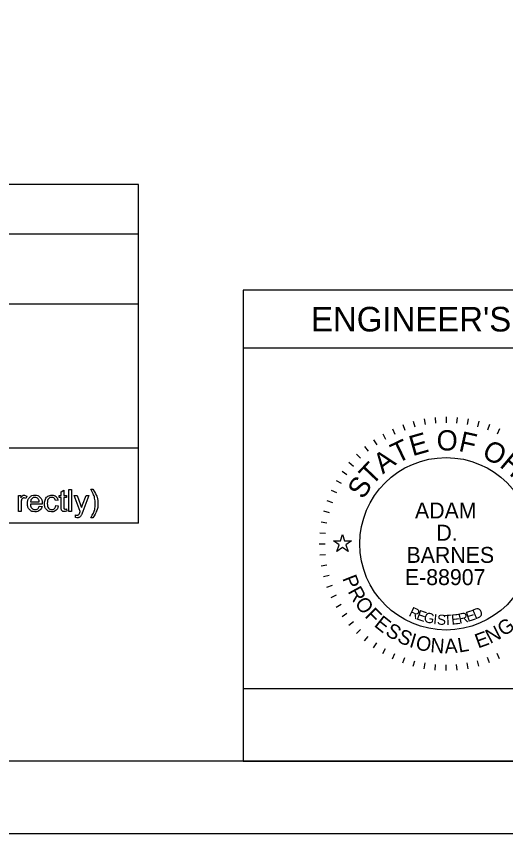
# Model space of a CAD drawing. Extents: x 0 to 34, y 0 to 22.
# Drawn here: x 5.78 to 9.16, y 0 to 5.64 of the extents above; entities that cross this region are included whole.
import ezdxf

# ---------------------------------------------------------------- set-up
doc = ezdxf.new("R2010")
doc.units = 0
for name, color, linetype in [('Default', 7, 'Continuous'), ('SH_Border', 7, 'Continuous'), ('SH_Cut_Line', 7, 'Continuous'), ('SH_Data', 7, 'Continuous'), ('SH_Text', 7, 'Continuous')]:
    doc.layers.add(name, color=color, linetype=linetype)

msp = doc.modelspace()

# ---------------------------------------------------------------- linework, layer by layer
at = {"layer": 'Default'}
msp.add_lwpolyline([(7.9736, 2.02), (8.0205, 2.02), (8.035, 2.0645), (8.0495, 2.02), (8.0964, 2.02), (8.0585, 1.9924), (8.073, 1.9478), (8.035, 1.9754), (7.997, 1.9478), (8.0115, 1.9924)], close=True, dxfattribs=at)
at = {"layer": 'SH_Border'}
msp.add_lwpolyline([(1.5, 21.5), (33.5, 21.5), (33.5, 0.5), (1.5, 0.5)], close=True, dxfattribs=at)
at = {"layer": 'SH_Cut_Line'}
msp.add_lwpolyline([(0, 0), (34, 0), (34, 22), (0, 22)], close=True, dxfattribs=at)
at = {"layer": 'SH_Data'}
for p, q in [((6.6275, 4.4803), (2.3775, 4.4803)), ((6.6275, 2.1428), (6.6275, 4.4803)), ((2.3775, 4.1387), (6.6275, 4.1387)), ((10.15, 3.75), (7.35, 3.75)), ((7.35, 3.75), (7.35, 0.5)), ((2.3775, 3.6553), (6.6275, 3.6553)), ((10.15, 3.35), (7.35, 3.35)), ((8.4507, 2.8222), (8.4644, 2.7846)), ((8.5235, 2.8452), (8.5339, 2.8065)), ((8.5981, 2.8617), (8.605, 2.8223)), ((8.6737, 2.8717), (8.6772, 2.8318)), ((8.75, 2.875), (8.75, 2.835)), ((8.8263, 2.8717), (8.8228, 2.8318)), ((8.9019, 2.8617), (8.895, 2.8223)), ((8.9765, 2.8452), (8.9661, 2.8065)), ((9.0493, 2.8222), (9.0356, 2.7846)), ((8.3802, 2.793), (8.3971, 2.7568)), ((9.1198, 2.793), (9.1029, 2.7568)), ((8.2481, 2.7168), (8.2711, 2.684)), ((8.3125, 2.7578), (8.3325, 2.7231)), ((6.6275, 2.6607), (2.3775, 2.6607)), ((8.1876, 2.6703), (8.2133, 2.6396)), ((8.1313, 2.6187), (8.1596, 2.5904)), ((8.0797, 2.5624), (8.1104, 2.5367)), ((8.0332, 2.5019), (8.066, 2.4789)), ((7.9922, 2.4375), (8.0269, 2.4175)), ((7.957, 2.3698), (7.9932, 2.3529)), ((7.9278, 2.2993), (7.9654, 2.2856)), ((7.9048, 2.2265), (7.9435, 2.2161)), ((7.8883, 2.1519), (7.9277, 2.145)), ((6.6275, 2.1428), (2.3775, 2.1428)), ((7.8783, 2.0763), (7.9182, 2.0728)), ((7.875, 2), (7.915, 2)), ((7.8783, 1.9237), (7.9182, 1.9272)), ((7.8883, 1.8481), (7.9277, 1.855)), ((7.9048, 1.7735), (7.9435, 1.7839)), ((7.9278, 1.7007), (7.9654, 1.7144)), ((7.957, 1.6302), (7.9932, 1.6471)), ((7.9922, 1.5625), (8.0269, 1.5825)), ((8.0332, 1.4981), (8.066, 1.5211)), ((8.0797, 1.4376), (8.1104, 1.4633)), ((8.1313, 1.3813), (8.1596, 1.4096)), ((8.1876, 1.3297), (8.2133, 1.3604)), ((8.2481, 1.2832), (8.2711, 1.316)), ((8.3125, 1.2422), (8.3325, 1.2769)), ((8.3802, 1.207), (8.3971, 1.2432)), ((9.1198, 1.207), (9.1029, 1.2432)), ((8.4507, 1.1778), (8.4644, 1.2154)), ((8.5235, 1.1548), (8.5339, 1.1935)), ((8.9765, 1.1548), (8.9661, 1.1935)), ((9.0493, 1.1778), (9.0356, 1.2154)), ((8.5981, 1.1383), (8.605, 1.1777)), ((8.6737, 1.1283), (8.6772, 1.1682)), ((8.75, 1.125), (8.75, 1.165)), ((8.8263, 1.1283), (8.8228, 1.1682)), ((8.9019, 1.1383), (8.895, 1.1777)), ((10.15, 0.5), (7.35, 0.5))]:
    msp.add_line(p, q, dxfattribs=at)
msp.add_lwpolyline([(10.15, 0.5), (10.15, 1), (7.35, 1), (7.35, 0.5)], close=True, dxfattribs=at)
msp.add_circle((8.75, 2), 0.595, dxfattribs=at)
at = {"layer": 'SH_Text'}
for points in [[(6.092, 2.2558), (6.092, 2.3185), (6.0784, 2.3185), (6.0784, 2.3328), (6.092, 2.3328), (6.092, 2.3597), (6.1105, 2.3708), (6.1105, 2.3328), (6.1289, 2.3328), (6.1289, 2.3185), (6.1105, 2.3185), (6.1105, 2.2547)], [(6.1465, 2.2239), (6.1465, 2.3741), (6.1649, 2.3741), (6.1649, 2.2239), (6.1465, 2.2239)], [(6.2974, 2.3766), (6.3105, 2.3766)], [(5.7971, 2.2239), (5.7971, 2.3328), (5.8137, 2.3328), (5.8137, 2.3163)], [(5.8562, 2.3293), (5.8497, 2.3122)], [(6.2243, 2.2238), (6.183, 2.3328), (6.2029, 2.3328), (6.2255, 2.2699)], [(6.241, 2.2693), (6.2643, 2.3328), (6.2827, 2.3328), (6.2414, 2.222)], [(5.8155, 2.2809), (5.8155, 2.2239), (5.7971, 2.2239)], [(5.9611, 2.2736), (5.88, 2.2736)], [(5.881, 2.2887), (5.9418, 2.2887)], [(5.9416, 2.2591), (5.9606, 2.2567)], [(6.0712, 2.3007), (6.0532, 2.298)], [(6.0548, 2.2638), (6.0729, 2.2613)], [(6.1289, 2.2404), (6.1315, 2.2241)], [(6.1928, 2.1821), (6.1907, 2.1995)], [(6.3105, 2.1798), (6.2974, 2.1798)]]:
    msp.add_lwpolyline(points, dxfattribs=at)
for points in [[(6.2974, 2.1798), (6.3279, 2.2289), (6.3279, 2.2782), (6.3279, 2.2974), (6.3235, 2.3164), (6.32, 2.3317), (6.3138, 2.3459), (6.3098, 2.3551), (6.2974, 2.3766)], [(6.3105, 2.3766), (6.3298, 2.3509), (6.339, 2.325), (6.3469, 2.3026), (6.3469, 2.2783), (6.3469, 2.2506), (6.3363, 2.2248), (6.3257, 2.199), (6.3105, 2.1798)], [(5.8137, 2.3163), (5.8201, 2.3278), (5.8254, 2.3315), (5.8308, 2.3352), (5.8372, 2.3352), (5.8466, 2.3352), (5.8562, 2.3293)], [(5.8497, 2.3122), (5.843, 2.3162), (5.8363, 2.3162), (5.8302, 2.3162), (5.8255, 2.3125), (5.8207, 2.3089), (5.8186, 2.3024), (5.8155, 2.2926), (5.8155, 2.2809)], [(5.9606, 2.2567), (5.9561, 2.24), (5.9439, 2.2307), (5.9317, 2.2215), (5.9128, 2.2215), (5.8889, 2.2215), (5.875, 2.2362), (5.861, 2.2509), (5.861, 2.2774), (5.861, 2.3049), (5.8751, 2.32), (5.8892, 2.3352), (5.9118, 2.3352), (5.9336, 2.3352), (5.9474, 2.3203), (5.9612, 2.3055), (5.9612, 2.2785), (5.9612, 2.2769), (5.9611, 2.2736)], [(5.9418, 2.2887), (5.9405, 2.3025), (5.9348, 2.3094), (5.926, 2.3201), (5.912, 2.3201), (5.8993, 2.3201), (5.8906, 2.3115), (5.8819, 2.303), (5.881, 2.2887)], [(6.0729, 2.2613), (6.07, 2.2427), (6.0577, 2.2321), (6.0455, 2.2215), (6.0277, 2.2215), (6.0053, 2.2215), (5.9917, 2.2361), (5.9782, 2.2507), (5.9782, 2.2779), (5.9782, 2.2955), (5.984, 2.3088), (5.9899, 2.322), (6.0018, 2.3286), (6.0137, 2.3352), (6.0278, 2.3352), (6.0455, 2.3352), (6.0568, 2.3262), (6.068, 2.3172), (6.0712, 2.3007)], [(6.0532, 2.298), (6.0507, 2.309), (6.0442, 2.3145), (6.0377, 2.3201), (6.0285, 2.3201), (6.0146, 2.3201), (6.0059, 2.3101), (5.9972, 2.3001), (5.9972, 2.2784), (5.9972, 2.2565), (6.0056, 2.2466), (6.014, 2.2366), (6.0275, 2.2366), (6.0384, 2.2366), (6.0456, 2.2433), (6.0529, 2.2499), (6.0548, 2.2638)], [(5.88, 2.2736), (5.881, 2.2557), (5.8901, 2.2462), (5.8992, 2.2366), (5.9129, 2.2366), (5.923, 2.2366), (5.9302, 2.242), (5.9374, 2.2473), (5.9416, 2.2591)], [(6.2255, 2.2699), (6.2299, 2.258), (6.2334, 2.2448), (6.2366, 2.2572), (6.241, 2.2693)], [(6.1315, 2.2241), (6.1238, 2.2224), (6.1176, 2.2224), (6.1076, 2.2224), (6.1021, 2.2256), (6.0965, 2.2288), (6.0943, 2.234), (6.092, 2.2392), (6.092, 2.2558)], [(6.1105, 2.2547), (6.1105, 2.2468), (6.1114, 2.2445), (6.1124, 2.2423), (6.1146, 2.2409), (6.1168, 2.2396), (6.1209, 2.2396), (6.1239, 2.2396), (6.1289, 2.2404)], [(6.1907, 2.1995), (6.1967, 2.1978), (6.2012, 2.1978), (6.2074, 2.1978), (6.211, 2.1999), (6.2147, 2.2019), (6.2171, 2.2056), (6.2188, 2.2084), (6.2227, 2.2193), (6.2232, 2.2209), (6.2243, 2.2238)], [(6.2414, 2.222), (6.2348, 2.2042), (6.2311, 2.1974), (6.2262, 2.1883), (6.2198, 2.1841), (6.2135, 2.1799), (6.2046, 2.1799), (6.1993, 2.1799), (6.1928, 2.1821)]]:
    msp.add_open_spline(points, degree=3, dxfattribs=at)

# ---------------------------------------------------------------- texts
at = {"layer": 'SH_Data'}
for s, height, p in [("ENGINEER'S SEAL", 0.17, (7.8176, 3.465)), ('ADAM', 0.11, (8.5353, 2.1749)), ('D.', 0.11, (8.6832, 2.0216)), ('BARNES', 0.11, (8.477, 1.8684)), ('E-88907', 0.11, (8.4659, 1.7151))]:
    msp.add_text(s, height=height, dxfattribs=at).set_placement(p)
for s, height, rotation, p in [('E', 0.14, 15.7571, (8.5184, 2.6038)), ('O', 0.14, 359.7812, (8.6847, 2.6443)), ('F', 0.14, 347.4362, (8.8311, 2.6417)), ('T', 0.14, 25.7167, (8.4116, 2.5518)), ('O', 0.14, 332.2586, (8.9898, 2.6015)), ('A', 0.14, 36.4747, (8.3134, 2.4781)), ('H', 0.14, 319.9136, (9.1132, 2.5361)), ('T', 0.14, 46.4344, (8.2383, 2.3964)), ('S', 0.14, 57.1924, (8.1781, 2.3014)), ('P', 0.1, 291.494, (8.0323, 1.7621)), ('R', 0.1, 298.7311, (8.069, 1.6717)), ('O', 0.1, 306.4666, (8.1155, 1.5883)), ('F', 0.1, 314.7068, (8.1843, 1.4983)), ('R', 0.07, 334.487, (8.4875, 1.5051)), ('E', 0.07, 341.04, (8.5406, 1.4801)), ('G', 0.07, 347.4752, (8.5914, 1.4618)), ('R', 0.07, 11.9184, (8.8425, 1.4474)), ('E', 0.07, 17.6836, (8.8998, 1.4602)), ('D', 0.07, 23.3052, (8.951, 1.477)), ('E', 0.1, 321.4393, (8.2478, 1.4348)), ('I', 0.07, 353.7858, (8.6591, 1.4468)), ('S', 0.07, 356.8926, (8.6858, 1.4429)), ('T', 0.07, 3.0061, (8.7357, 1.4387)), ('E', 0.07, 6.0117, (8.7889, 1.4412)), ('G', 0.1, 35.0469, (9.1481, 1.357)), ('S', 0.1, 328.6764, (8.3243, 1.3752)), ('N', 0.1, 27.3113, (9.0545, 1.3075)), ('S', 0.1, 335.9134, (8.4064, 1.3266)), ('I', 0.1, 343.1505, (8.4906, 1.2897)), ('O', 0.1, 346.8859, (8.5339, 1.2751)), ('E', 0.1, 20.0742, (8.9712, 1.277)), ('N', 0.1, 355.1261, (8.6388, 1.2517)), ('A', 0.1, 2.8617, (8.7423, 1.2437)), ('L', 0.1, 10.0987, (8.8394, 1.249))]:
    msp.add_text(s, height=height, rotation=rotation, dxfattribs=at).set_placement(p)

doc.saveas('drawing.dxf')
